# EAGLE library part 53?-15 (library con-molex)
CONNECTOR wire to board 1.25 mm (.049 inch) pitch header
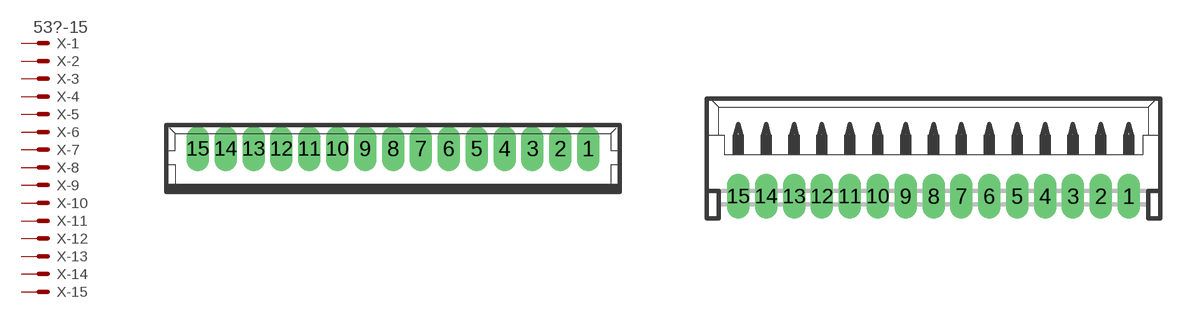
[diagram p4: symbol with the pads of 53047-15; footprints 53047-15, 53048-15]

Designator prefix X; gates -1=MV -2=M -3=M -4=M -5=M -6=M -7=M -8=M -9=M -10=M -11=M -12=M -13=M -14=M -15=M

## 53047-15 (MPN: 53047-1510-C; OC_FARNELL: unknown; OC_NEWARK: 79K4146)  [53047-15]
1  -1:S  pas
2  -2:S  pas
3  -3:S  pas
4  -4:S  pas
5  -5:S  pas
6  -6:S  pas
7  -7:S  pas
8  -8:S  pas
9  -9:S  pas
10  -10:S  pas
11  -11:S  pas
12  -12:S  pas
13  -13:S  pas
14  -14:S  pas
15  -15:S  pas

## 53048-15 (MPN: 53048-1510; OC_FARNELL: 9732942; OC_NEWARK: 98K9840)  [53048-15]
Pads as for 53047-15

## 53261-15 (OC_FARNELL: 1125365; OC_NEWARK: unknown)  [53261-15]
Pads as for 53047-15

## 53398-15 (MF: MOLEX; MPN: 53398-1590; OC_FARNELL: 1125358; OC_NEWARK: 57H5433)  [53398-15]
Pads as for 53047-15

## Footprint 53047-15 (pad centres in mm)
CONNECTOR wire to board 1.25 mm (.049 inch) pitch header straight Sourcxe: http://www.molex.com/pdm_docs/sd/530470210_sd.pdf
drill 0.5 pad 0.698 long: 1 8.75,0.45; 2 7.5,0.45; 3 6.25,0.45; 4 5,0.45; 5 3.75,0.45; 6 2.5,0.45; 7 1.25,0.45; 8 0,0.45; 9 -1.25,0.45; 10 -2.5,0.45; 11 -3.75,0.45; 12 -5,0.45; 13 -6.25,0.45; 14 -7.5,0.45; 15 -8.75,0.45

## Footprint 53048-15 (pad centres in mm)
CONNECTOR wire to board 1.25 mm (.049 inch) pitch header right angle
drill 0.5 pad 0.698 long: 1 8.75,-1.25; 2 7.5,-1.25; 3 6.25,-1.25; 4 5,-1.25; 5 3.75,-1.25; 6 2.5,-1.25; 7 1.25,-1.25; 8 0,-1.25; 9 -1.25,-1.25; 10 -2.5,-1.25; 11 -3.75,-1.25; 12 -5,-1.25; 13 -6.25,-1.25; 14 -7.5,-1.25; 15 -8.75,-1.25

## Footprint 53261-15 (pad centres in mm)
CONNECTOR wire to board 1.25 mm (.049 inch) pitch header SMT right angle
smd 0.8 x 2: 1 8.75,-2.5; 2 7.5,-2.5; 3 6.25,-2.5; 4 5,-2.5; 5 3.75,-2.5; 6 2.5,-2.5; 7 1.25,-2.5; 8 0,-2.5; 9 -1.25,-2.5; 10 -2.5,-2.5; 11 -3.75,-2.5; 12 -5,-2.5; 13 -6.25,-2.5; 14 -7.5,-2.5; 15 -8.75,-2.5
smd 2.1 x 3: S1 11.25,0.625; S2 -11.25,0.625

## Footprint 53398-15 (pad centres in mm)
CONNECTOR wire to board 1.25 mm (.049 inch) pitch header SMT straight
smd 0.8 x 1.8: 1 8.75,-2.5; 2 7.5,-2.5; 3 6.25,-2.5; 4 5,-2.5; 5 3.75,-2.5; 6 2.5,-2.5; 7 1.25,-2.5; 8 0,-2.5; 9 -1.25,-2.5; 10 -2.5,-2.5; 11 -3.75,-2.5; 12 -5,-2.5; 13 -6.25,-2.5; 14 -7.5,-2.5; 15 -8.75,-2.5
smd 2.1 x 3: S1 11.25,0.625; S2 -11.25,0.625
